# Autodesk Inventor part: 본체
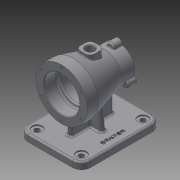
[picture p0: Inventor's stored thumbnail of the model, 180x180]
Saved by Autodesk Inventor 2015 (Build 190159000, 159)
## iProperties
Created: 2021-10
Part Number: 본체
Material: 일반
Document SubType Name: Modeling
Designer: pc-04
Density: 1 g/cm^3
Appearance: 기본값
Author: pc-04
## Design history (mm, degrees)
sketch "스케치1"
  geometry: L1 (0, 50)-(0, -50); L2 (0, 50)-(45, 50); L3 (45, 50)-(45, 30); L4 (45, 30)-(29, -27); L5 (29, -27)-(29, -50); L6 (29, -50)-(0, -50); 2 further points
  constraints: 12 end point, 2 coincident, 2 perpendicular, 1 horizontal, 1 midpoint, 1 parallel, 1 vertical
  dimensions: "d0" = 90 diameter of L3 L1; "d1" = 20 distance of L2.end L3.end; "d2" = 23 distance of L4.end L5.end; "d3" = 58 diameter of L5 L1; "d4" = 100 distance of L1.start L1.end
revolve "회전1" sketch "스케치1" stored, may be unused: angle "d5" = 90 deg
sketch "스케치2"
  geometry: L1 (0, 50)-(31, 50); L2 (-45, 50)-(45, 50) reference; L3 (31, 30)-(31, 50); L4 (28, 27)-(28, 27); L5 (25, 24)-(25, -17); L6 (22, -20)-(22, -20); L7 (19, -23)-(19, -50); L8 (19, -50)-(0, -50); L9 (0, 50)-(0, -50); A1 r 3 centre (28, 30) between (28, 27) and (31, 30); A2 r 3 centre (28, 24) between (28, 27) and (25, 24); A3 r 3 centre (22, -17) between (22, -20) and (25, -17); A4 r 3 centre (22, -23) between (22, -20) and (19, -23); 6 further points
  constraints: 16 end point, 9 point on line, 8 point on circle, 8 tangent, 5 perpendicular, 4 centre point, 3 equal radius, 1 coincident, 1 horizontal, 1 midpoint, 1 vertical
  dimensions: "d6" = 23 distance of point (31, 27) L1.end; "d7" = 47 distance of point (25, 27) point (25, -20); "d8" = 30 distance of point (19, -20) L7.end; "d9" = 62 diameter of L3 L9; "d10" = 50 diameter of L5 L9; "d11" = 38 diameter of L7 L9; "d12" = 3 radius of A1
revolve "회전2" sketch "스케치2" stored, may be unused: angle "d13" = 90 deg
chamfer "모따기1" distance "d14" = 1; stored, may be unused: second distance "d15" = 2, angle "d16" = 45 deg
chamfer "모따기2" distance "d17" = 1; stored, may be unused: second distance "d18" = 2, angle "d19" = 45 deg
sketch "스케치3" dims "d20" = 58
  geometry: C1 r 7 at (0, 29); 2 further points
  constraints: 2 vertical alignment, 1 centre point, 1 coincident, 2 other
  dimensions: "d21" = 14 diameter of C1
extrude "돌출1" join sketch "스케치3" distance "d22" = 15; taper "d23" = 0 deg
fillet "모깎기1" dims "d24" = 1, "d25" = 3
sketch "스케치4"
  geometry: 2 further points
hole "구멍1" sketch "스케치4" at (0, 0) diameter "d26" = 3.242; stored, may be unused: countersink angle "d30" = 90 deg, drill point angle "d32" = 118 deg; dims "d27" = 9, "d28" = 4, "d29" = 2, "d31" = 11
node "작업 평면1"
sketch "스케치5"
  geometry: L1 (12.5, 12.5)-(-12.5, 12.5); L2 (-12.5, 12.5)-(-12.5, -12.5); L3 (-12.5, -12.5)-(12.5, -12.5); L4 (12.5, -12.5)-(12.5, 12.5); 3 further points
  constraints: 8 end point, 2 midpoint, 2 parallel, 1 horizontal, 1 horizontal alignment, 1 perpendicular, 1 vertical alignment
  dimensions: "d37" = 25 distance of L2.end L3.end; "d38" = 25 distance of L3.end L1.start
extrude "돌출2" join sketch "스케치5" stored distance "d39" = 15; taper "d40" = 0 deg
fillet "모깎기2" dims "d41" = 8
fillet "모깎기3" dims "d42" = 1
sketch "스케치6"
  geometry: C1 r 7.5 at (0, 0); 1 further point
  constraints: 1 centre point, 1 coincident
  dimensions: "d43" = 15 diameter of C1
extrude "돌출3" cut sketch "스케치6" stored distance "d44" = 15; taper "d45" = 0 deg
chamfer "모따기3" distance "d46" = 1; stored, may be unused: second distance "d47" = 2, angle "d48" = 45 deg
sketch "스케치7" dims "d49" = 80
  geometry: 3 further points
  constraints: 2 vertical alignment, 1 coincident, 2 other
hole "구멍2" sketch "스케치7" at (0, 40) diameter "d50" = 3.242; stored, may be unused: countersink angle "d54" = 90 deg, drill point angle "d56" = 118 deg; dims "d51" = 9, "d52" = 4, "d53" = 2, "d55" = 11
node "작업 평면2"
sketch "스케치8"
  geometry: L1 (55, 70)-(-55, 70); L2 (-55, 70)-(-55, -70); L3 (-55, -70)-(55, -70); L4 (55, -70)-(55, 70); 3 further points
  constraints: 8 end point, 2 midpoint, 2 parallel, 1 horizontal, 1 horizontal alignment, 1 perpendicular, 1 vertical alignment
  dimensions: "d61" = 140 distance of L3.end L1.start; "d62" = 110 distance of L1.start L1.end
extrude "돌출4" join sketch "스케치8" distance "d63" = 12; taper "d64" = 0 deg
fillet "모깎기4" dims "d65" = 16
sketch "스케치9"
  geometry: L1 (55, -54)-(55, 54) reference; L2 (39, 70)-(-39, 70) reference; L3 (-39, -70)-(39, -70) reference; A1 r 16 centre (-39, 54) between (-39, 70) and (-55, 54) reference; 5 further points
  constraints: 1 coincident
  dimensions: "d66" = 16 distance from line of L1 point (39, 54); "d67" = 16 distance from line of L2 point (39, 54); "d68" = 108 distance of point (-39, -54) point (-39, 54); "d69" = 16 distance from line of L3 point (-39, -54); "d70" = 16 distance from line of L1 point (39, -54); "d71" = 78 distance of point (39, -54) point (-39, -54)
hole "구멍3" sketch "스케치9" at (-39, 54), (39, 54), (39, -54), (-39, -54) diameter "d72" = 9; stored, may be unused: countersink angle "d76" = 90 deg, drill point angle "d78" = 118 deg; dims "d73" = 9, "d74" = 18, "d75" = 2, "d77" = 12
sketch "스케치10"
  geometry: L1 (-4, -37)-(4, -37); L2 (4, -37)-(4, 37); L3 (4, 37)-(-4, 37); L4 (-4, 37)-(-4, -37); L5 (-24, -4)-(24, -4); L6 (24, -4)-(24, 4); L7 (24, 4)-(-24, 4); L8 (-24, 4)-(-24, -4); L9 (-39, -70)-(39, -70) reference; 3 further points
  constraints: 16 end point, 4 parallel, 2 horizontal, 2 midpoint, 2 perpendicular, 1 horizontal alignment, 1 vertical alignment
  dimensions: "d79" = 8 distance of L2.end L3.end; "d80" = 8 distance of L7.end L5.start; "d81" = 33 distance between parallel lines of L9 L1; "d82" = 74 distance of L3.end L1.start; "d83" = 24 distance from line of L8 point (0, 0); "d84" = 24 distance from line of L6 point (0, 0)
extrude "돌출5" join sketch "스케치10" stored distance "d85" = 2; taper "d86" = 0 deg
feature "면 기울기1" dims angle "d87" = 5 deg
feature "면 기울기2" dims angle "d88" = 5 deg
fillet "모깎기5" dims "d89" = 3
fillet "모깎기6" dims "d90" = 3, "d91" = 3
fillet "모깎기7" dims "d92" = 3
sketch "스케치11"
  geometry: L1 (39, 70)-(-39, 70) reference; L2 (55, -54)-(55, 54) reference; L3 (-39, -70)-(39, -70) reference; L4 (-55, 54)-(-55, -54) reference; C1 r 4.5 at (39, -54) reference; C2 r 4.5 at (-39, 54) reference; C3 r 4.5 at (39, 54) reference; C4 r 4.5 at (-39, -54) reference; A1 r 16 centre (-39, 54) between (-39, 70) and (-55, 54) reference; A2 r 16 centre (39, 54) between (55, 54) and (39, 70) reference; A3 r 16 centre (39, -54) between (39, -70) and (55, -54) reference; A4 r 16 centre (-39, -54) between (-55, -54) and (-39, -70) reference; 2 further points
  constraints: 1 horizontal alignment, 1 other
  dimensions: "d93" = 15 distance from line of L2 point (40, 0)
extrude "돌출6" join sketch "스케치11" distance "d94" = 0.5; taper "d95" = 0 deg
node "솔리드1"
pattern_circular "원형 패턴1" dims "d34" = 360 deg
pattern_circular "원형 패턴2" dims angle "d58" = 360 deg
node "투영된 루프1"
other parameters: "d36" = 45, "d60" = -82
